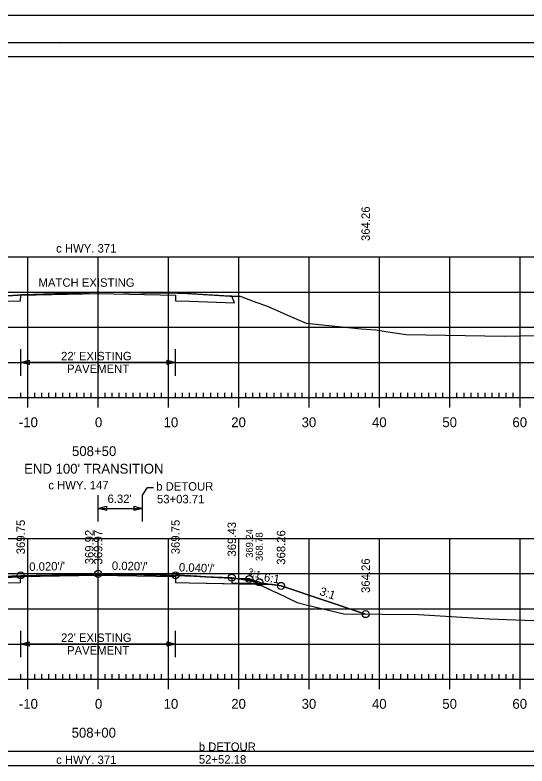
# Model space of a CAD drawing. Extents: x 1368910 to 1369601, y 380116 to 380950.
# Drawn here: x 1369068.4 to 1369141.2, y 380630.4 to 380737.1 of the extents above; entities that cross this region are included whole.
import ezdxf

# ---------------------------------------------------------------- set-up
doc = ezdxf.new("R2010")
doc.units = 0
for name, color, linetype in [('_STAGE 1 CUT', 7, 'Continuous'), ('_STAGE 1 FILL', 7, 'Continuous'), ('_STAGE 2 CUT', 7, 'Continuous'), ('_STAGE 3 CUT', 7, 'Continuous'), ('Default', 7, 'Continuous'), ('Notes', 7, 'Continuous'), ('R_Alt Surface', 7, 'Continuous'), ('R_Axis', 7, 'Continuous'), ('R_Axis Annot', 7, 'Continuous'), ('R_Border', 7, 'Continuous'), ('R_Border Plan-Plan', 7, 'Continuous'), ('R_Detour Surface', 7, 'Continuous'), ('R_Exist Surface', 7, 'Continuous'), ('R_Fin Surface', 7, 'Continuous'), ('R_Grid', 7, 'Continuous'), ('R_No Plot', 7, 'Continuous'), ('R_ROW Annot', 7, 'Continuous'), ('R_Xsect Elev', 7, 'Continuous'), ('R_Xsect Elev Detour', 7, 'Continuous'), ('R_Xsect Slope', 7, 'Continuous')]:
    doc.layers.add(name, color=color, linetype=linetype)

msp = doc.modelspace()

# ---------------------------------------------------------------- linework, layer by layer
at = {"layer": '_STAGE 1 CUT'}
for p, q in [((1369080.24, 380697.72), (1369080.24, 380697.55)), ((1369099.61, 380696.25), (1369099.25, 380697.17)), ((1369101.65, 380656.92), (1369101.64, 380656.93)), ((1369101.64, 380656.92), (1369101.65, 380656.92))]:
    msp.add_line(p, q, dxfattribs=at)
for points in [[(1369092.12, 380697.59), (1369091.55, 380697.62), (1369090.81, 380697.65), (1369090.64, 380697.65), (1369086.38, 380697.65), (1369086.34, 380697.65), (1369084.01, 380697.7), (1369083.9, 380697.71), (1369080.24, 380697.72)], [(1369080.24, 380697.55), (1369091.24, 380697.33), (1369091.25, 380696.5), (1369093.24, 380696.46), (1369099.61, 380696.25)], [(1369099.25, 380697.17), (1369099.24, 380697.17), (1369099.03, 380697.16), (1369098.12, 380697.22), (1369093.51, 380697.5), (1369092.12, 380697.59)], [(1369101.65, 380656.92), (1369101.64, 380656.93), (1369101.25, 380656.95), (1369100.27, 380657.02), (1369099.24, 380657.09), (1369099.03, 380657.1), (1369095.52, 380657.31), (1369094.27, 380657.39), (1369091.62, 380657.54), (1369091.24, 380657.56)], [(1369091.24, 380657.56), (1369091.24, 380657.51), (1369091.24, 380657.34)], [(1369091.24, 380657.34), (1369091.25, 380656.51), (1369093.24, 380656.47), (1369103.06, 380656.27)], [(1369101.64, 380656.93), (1369101.64, 380656.92)], [(1369103.06, 380656.27), (1369102.88, 380656.36), (1369102.25, 380656.66), (1369102.16, 380656.7), (1369101.65, 380656.92)]]:
    msp.add_lwpolyline(points, dxfattribs=at)
at = {"layer": '_STAGE 1 FILL'}
for p, q in [((1369104.97, 380656.23), (1369103.06, 380656.27)), ((1369103.06, 380656.27), (1369105.11, 380655.28))]:
    msp.add_line(p, q, dxfattribs=at)
for points in [[(1369118.26, 380652.01), (1369106.24, 380656.02), (1369104.97, 380656.23)], [(1369105.11, 380655.28), (1369105.71, 380655.03), (1369108.53, 380653.67), (1369110.01, 380653.27), (1369115.17, 380652.04), (1369118.26, 380652.01)]]:
    msp.add_lwpolyline(points, dxfattribs=at)
at = {"layer": '_STAGE 2 CUT'}
msp.add_line((1369080.24, 380697.55), (1369080.24, 380697.72), dxfattribs=at)
for points in [[(1369060.88, 380696.25), (1369067.24, 380696.46), (1369069.23, 380696.5), (1369069.24, 380697.33), (1369080.24, 380697.55)], [(1369080.09, 380697.72), (1369075.66, 380697.55), (1369075.58, 380697.54), (1369075.44, 380697.54), (1369069.62, 380697.38), (1369069.59, 380697.38), (1369069.38, 380697.37), (1369068.82, 380697.33), (1369062.24, 380696.88), (1369060.95, 380696.42)], [(1369080.19, 380697.72), (1369080.12, 380697.72), (1369080.09, 380697.72)], [(1369080.24, 380697.72), (1369080.21, 380697.72), (1369080.19, 380697.72)], [(1369069.24, 380657.33), (1369067.22, 380657.2), (1369062.25, 380656.95), (1369060.72, 380656.34)], [(1369067.24, 380656.47), (1369069.23, 380656.51), (1369069.24, 380657.33)]]:
    msp.add_lwpolyline(points, dxfattribs=at)
at = {"layer": '_STAGE 3 CUT'}
for points in [[(1369103.14, 380656.54), (1369101.74, 380657), (1369099.9, 380657.08)], [(1369099.9, 380657.08), (1369100.27, 380657.02), (1369102.16, 380656.7), (1369103.14, 380656.54)]]:
    msp.add_lwpolyline(points, dxfattribs=at)
at = {"layer": 'Default'}
msp.add_line((1369080.24, 380667.02), (1369086.56, 380667.02), dxfattribs=at)
msp.add_lwpolyline([(1369086.56, 380668.9), (1369087.24, 380670.01), (1369088.12, 380670.01)], dxfattribs=at)
at = {"layer": 'R_Alt Surface'}
for points in [[(1369055.52, 380656.23), (1369067.24, 380656.47), (1369069.23, 380656.51), (1369069.24, 380657.34), (1369080.24, 380657.56), (1369091.24, 380657.34), (1369091.25, 380656.51), (1369093.24, 380656.47), (1369104.97, 380656.23)], [(1369099.24, 380657.1), (1369099.24, 380656.43), (1369103.73, 380656.34)]]:
    msp.add_lwpolyline(points, dxfattribs=at)
at = {"layer": 'R_Axis'}
for p, q in [((1369070.24, 380681.36), (1369070.24, 380684.16)), ((1369080.24, 380681.36), (1369080.24, 380684.16)), ((1369090.24, 380681.36), (1369090.24, 380684.16)), ((1369100.24, 380681.36), (1369100.24, 380684.16)), ((1369110.24, 380681.36), (1369110.24, 380684.16)), ((1369120.24, 380681.36), (1369120.24, 380684.16)), ((1369130.24, 380681.36), (1369130.24, 380684.16)), ((1369140.24, 380681.36), (1369140.24, 380684.16)), ((1368940.24, 380682.76), (1369220.24, 380682.76)), ((1369069.24, 380682.76), (1369069.24, 380683.46)), ((1369071.24, 380682.76), (1369071.24, 380683.46)), ((1369072.24, 380682.76), (1369072.24, 380683.46)), ((1369073.24, 380682.76), (1369073.24, 380683.46)), ((1369074.24, 380682.76), (1369074.24, 380683.46)), ((1369075.24, 380682.76), (1369075.24, 380683.46)), ((1369076.24, 380682.76), (1369076.24, 380683.46)), ((1369077.24, 380682.76), (1369077.24, 380683.46)), ((1369078.24, 380682.76), (1369078.24, 380683.46)), ((1369079.24, 380682.76), (1369079.24, 380683.46)), ((1369081.24, 380682.76), (1369081.24, 380683.46)), ((1369082.24, 380682.76), (1369082.24, 380683.46)), ((1369083.24, 380682.76), (1369083.24, 380683.46)), ((1369084.24, 380682.76), (1369084.24, 380683.46)), ((1369085.24, 380682.76), (1369085.24, 380683.46)), ((1369086.24, 380682.76), (1369086.24, 380683.46)), ((1369087.24, 380682.76), (1369087.24, 380683.46)), ((1369088.24, 380682.76), (1369088.24, 380683.46)), ((1369089.24, 380682.76), (1369089.24, 380683.46)), ((1369091.24, 380682.76), (1369091.24, 380683.46)), ((1369092.24, 380682.76), (1369092.24, 380683.46)), ((1369093.24, 380682.76), (1369093.24, 380683.46)), ((1369094.24, 380682.76), (1369094.24, 380683.46)), ((1369095.24, 380682.76), (1369095.24, 380683.46)), ((1369096.24, 380682.76), (1369096.24, 380683.46)), ((1369097.24, 380682.76), (1369097.24, 380683.46)), ((1369098.24, 380682.76), (1369098.24, 380683.46)), ((1369099.24, 380682.76), (1369099.24, 380683.46)), ((1369101.24, 380682.76), (1369101.24, 380683.46)), ((1369102.24, 380682.76), (1369102.24, 380683.46)), ((1369103.24, 380682.76), (1369103.24, 380683.46)), ((1369104.24, 380682.76), (1369104.24, 380683.46)), ((1369105.24, 380682.76), (1369105.24, 380683.46)), ((1369106.24, 380682.76), (1369106.24, 380683.46)), ((1369107.24, 380682.76), (1369107.24, 380683.46)), ((1369108.24, 380682.76), (1369108.24, 380683.46)), ((1369109.24, 380682.76), (1369109.24, 380683.46)), ((1369111.24, 380682.76), (1369111.24, 380683.46)), ((1369112.24, 380682.76), (1369112.24, 380683.46)), ((1369113.24, 380682.76), (1369113.24, 380683.46)), ((1369114.24, 380682.76), (1369114.24, 380683.46)), ((1369115.24, 380682.76), (1369115.24, 380683.46)), ((1369116.24, 380682.76), (1369116.24, 380683.46)), ((1369117.24, 380682.76), (1369117.24, 380683.46)), ((1369118.24, 380682.76), (1369118.24, 380683.46)), ((1369119.24, 380682.76), (1369119.24, 380683.46)), ((1369121.24, 380682.76), (1369121.24, 380683.46)), ((1369122.24, 380682.76), (1369122.24, 380683.46)), ((1369123.24, 380682.76), (1369123.24, 380683.46)), ((1369124.24, 380682.76), (1369124.24, 380683.46)), ((1369125.24, 380682.76), (1369125.24, 380683.46)), ((1369126.24, 380682.76), (1369126.24, 380683.46)), ((1369127.24, 380682.76), (1369127.24, 380683.46)), ((1369128.24, 380682.76), (1369128.24, 380683.46)), ((1369129.24, 380682.76), (1369129.24, 380683.46)), ((1369131.24, 380682.76), (1369131.24, 380683.46)), ((1369132.24, 380682.76), (1369132.24, 380683.46)), ((1369133.24, 380682.76), (1369133.24, 380683.46)), ((1369134.24, 380682.76), (1369134.24, 380683.46)), ((1369135.24, 380682.76), (1369135.24, 380683.46)), ((1369136.24, 380682.76), (1369136.24, 380683.46)), ((1369137.24, 380682.76), (1369137.24, 380683.46)), ((1369138.24, 380682.76), (1369138.24, 380683.46)), ((1369139.24, 380682.76), (1369139.24, 380683.46)), ((1369070.24, 380641.36), (1369070.24, 380644.16)), ((1369080.24, 380641.36), (1369080.24, 380644.16)), ((1369090.24, 380641.36), (1369090.24, 380644.16)), ((1369100.24, 380641.36), (1369100.24, 380644.16)), ((1369110.24, 380641.36), (1369110.24, 380644.16)), ((1369120.24, 380641.36), (1369120.24, 380644.16)), ((1369130.24, 380641.36), (1369130.24, 380644.16)), ((1369140.24, 380641.36), (1369140.24, 380644.16)), ((1369069.24, 380642.76), (1369069.24, 380643.46)), ((1369071.24, 380642.76), (1369071.24, 380643.46)), ((1369072.24, 380642.76), (1369072.24, 380643.46)), ((1369073.24, 380642.76), (1369073.24, 380643.46)), ((1369074.24, 380642.76), (1369074.24, 380643.46)), ((1369075.24, 380642.76), (1369075.24, 380643.46)), ((1369076.24, 380642.76), (1369076.24, 380643.46)), ((1369077.24, 380642.76), (1369077.24, 380643.46)), ((1369078.24, 380642.76), (1369078.24, 380643.46)), ((1369079.24, 380642.76), (1369079.24, 380643.46)), ((1369081.24, 380642.76), (1369081.24, 380643.46)), ((1369082.24, 380642.76), (1369082.24, 380643.46)), ((1369083.24, 380642.76), (1369083.24, 380643.46)), ((1369084.24, 380642.76), (1369084.24, 380643.46)), ((1369085.24, 380642.76), (1369085.24, 380643.46)), ((1369086.24, 380642.76), (1369086.24, 380643.46)), ((1369087.24, 380642.76), (1369087.24, 380643.46)), ((1369088.24, 380642.76), (1369088.24, 380643.46)), ((1369089.24, 380642.76), (1369089.24, 380643.46)), ((1369091.24, 380642.76), (1369091.24, 380643.46)), ((1369092.24, 380642.76), (1369092.24, 380643.46)), ((1369093.24, 380642.76), (1369093.24, 380643.46)), ((1369094.24, 380642.76), (1369094.24, 380643.46)), ((1369095.24, 380642.76), (1369095.24, 380643.46)), ((1369096.24, 380642.76), (1369096.24, 380643.46)), ((1369097.24, 380642.76), (1369097.24, 380643.46)), ((1369098.24, 380642.76), (1369098.24, 380643.46)), ((1369099.24, 380642.76), (1369099.24, 380643.46)), ((1369101.24, 380642.76), (1369101.24, 380643.46)), ((1369102.24, 380642.76), (1369102.24, 380643.46)), ((1369103.24, 380642.76), (1369103.24, 380643.46)), ((1369104.24, 380642.76), (1369104.24, 380643.46)), ((1369105.24, 380642.76), (1369105.24, 380643.46)), ((1369106.24, 380642.76), (1369106.24, 380643.46)), ((1369107.24, 380642.76), (1369107.24, 380643.46)), ((1369108.24, 380642.76), (1369108.24, 380643.46)), ((1369109.24, 380642.76), (1369109.24, 380643.46)), ((1369111.24, 380642.76), (1369111.24, 380643.46)), ((1369112.24, 380642.76), (1369112.24, 380643.46)), ((1369113.24, 380642.76), (1369113.24, 380643.46)), ((1369114.24, 380642.76), (1369114.24, 380643.46)), ((1369115.24, 380642.76), (1369115.24, 380643.46)), ((1369116.24, 380642.76), (1369116.24, 380643.46)), ((1369117.24, 380642.76), (1369117.24, 380643.46)), ((1369118.24, 380642.76), (1369118.24, 380643.46)), ((1369119.24, 380642.76), (1369119.24, 380643.46)), ((1369121.24, 380642.76), (1369121.24, 380643.46)), ((1369122.24, 380642.76), (1369122.24, 380643.46)), ((1369123.24, 380642.76), (1369123.24, 380643.46)), ((1369124.24, 380642.76), (1369124.24, 380643.46)), ((1369125.24, 380642.76), (1369125.24, 380643.46)), ((1369126.24, 380642.76), (1369126.24, 380643.46)), ((1369127.24, 380642.76), (1369127.24, 380643.46)), ((1369128.24, 380642.76), (1369128.24, 380643.46)), ((1369129.24, 380642.76), (1369129.24, 380643.46)), ((1369131.24, 380642.76), (1369131.24, 380643.46)), ((1369132.24, 380642.76), (1369132.24, 380643.46)), ((1369133.24, 380642.76), (1369133.24, 380643.46)), ((1369134.24, 380642.76), (1369134.24, 380643.46)), ((1369135.24, 380642.76), (1369135.24, 380643.46)), ((1369136.24, 380642.76), (1369136.24, 380643.46)), ((1369137.24, 380642.76), (1369137.24, 380643.46)), ((1369138.24, 380642.76), (1369138.24, 380643.46)), ((1369139.24, 380642.76), (1369139.24, 380643.46)), ((1368940.24, 380642.76), (1369220.24, 380642.76))]:
    msp.add_line(p, q, dxfattribs=at)
at = {"layer": 'R_Border'}
for p, q in [((1368922.24, 380733.22), (1369238.42, 380733.22)), ((1369074.76, 380732.96), (1369074.76, 380732.96)), ((1369074.76, 380732.96), (1369074.76, 380732.96))]:
    msp.add_line(p, q, dxfattribs=at)
at = {"layer": 'R_Border Plan-Plan'}
msp.add_line((1368922.24, 380630.49), (1369238.42, 380630.49), dxfattribs=at)
at = {"layer": 'R_Detour Surface'}
msp.add_lwpolyline([(1369099.24, 380657.1), (1369101.74, 380657), (1369103.14, 380656.54), (1369103.73, 380656.34)], dxfattribs=at)
at = {"layer": 'R_Exist Surface'}
for points in [[(1369062.24, 380696.88), (1369068.82, 380697.33), (1369069.38, 380697.37), (1369069.59, 380697.38), (1369069.62, 380697.38), (1369075.44, 380697.54), (1369075.58, 380697.54), (1369075.66, 380697.55), (1369080.12, 380697.72), (1369080.19, 380697.72), (1369080.21, 380697.72), (1369083.9, 380697.71), (1369084.01, 380697.7), (1369086.34, 380697.65), (1369086.38, 380697.65), (1369090.64, 380697.65), (1369090.81, 380697.65), (1369091.55, 380697.62), (1369091.55, 380697.62), (1369092.12, 380697.59), (1369099.03, 380697.16), (1369099.61, 380697.18), (1369100.45, 380697.17), (1369102.3, 380696.47), (1369104.41, 380695.71), (1369107.04, 380694.5), (1369109.83, 380693.35), (1369117.62, 380692.51), (1369119.7, 380692.37), (1369121.13, 380692.17), (1369124.02, 380691.71), (1369129.59, 380691.65), (1369138.01, 380691.51), (1369148.63, 380691.72)], [(1369067.22, 380657.2), (1369069.54, 380657.35), (1369069.92, 380657.38), (1369070.52, 380657.38), (1369074.08, 380657.52), (1369074.69, 380657.54), (1369075.71, 380657.56), (1369079.62, 380657.65), (1369080.22, 380657.68), (1369080.5, 380657.69), (1369082.73, 380657.65), (1369085.59, 380657.63), (1369087.12, 380657.65), (1369089.07, 380657.62), (1369091.01, 380657.56), (1369091.62, 380657.54), (1369095.52, 380657.31), (1369099.03, 380657.1), (1369101.25, 380656.95), (1369101.64, 380656.93), (1369102.25, 380656.66), (1369105.11, 380655.28), (1369105.71, 380655.03), (1369108.53, 380653.67), (1369110.01, 380653.27), (1369115.17, 380652.04), (1369120.61, 380651.99), (1369125.77, 380651.94), (1369135.8, 380651.36), (1369143.39, 380651.06)]]:
    msp.add_lwpolyline(points, dxfattribs=at)
at = {"layer": 'R_Fin Surface'}
msp.add_lwpolyline([(1369034.95, 380652.59), (1369037.46, 380651.76), (1369041.46, 380651.76), (1369054.24, 380656.02), (1369055.52, 380656.23), (1369061.24, 380657.19), (1369069.24, 380657.51), (1369080.24, 380657.73), (1369091.24, 380657.51), (1369099.24, 380657.19), (1369104.97, 380656.23), (1369106.24, 380656.02), (1369118.26, 380652.01)], dxfattribs=at)
at = {"layer": 'R_Grid'}
for p, q in [((1368940.24, 380702.76), (1369220.24, 380702.76)), ((1369070.24, 380682.76), (1369070.24, 380702.76)), ((1369080.24, 380682.76), (1369080.24, 380702.76)), ((1369090.24, 380682.76), (1369090.24, 380702.76)), ((1369100.24, 380682.76), (1369100.24, 380702.76)), ((1369110.24, 380682.76), (1369110.24, 380702.76)), ((1369120.24, 380682.76), (1369120.24, 380702.76)), ((1369130.24, 380682.76), (1369130.24, 380702.76)), ((1369140.24, 380682.76), (1369140.24, 380702.76)), ((1368940.24, 380697.76), (1369220.24, 380697.76)), ((1368940.24, 380692.76), (1369220.24, 380692.76)), ((1368940.24, 380687.76), (1369220.24, 380687.76)), ((1368940.24, 380682.76), (1369220.24, 380682.76)), ((1368940.24, 380662.76), (1369220.24, 380662.76)), ((1369070.24, 380642.76), (1369070.24, 380662.76)), ((1369080.24, 380642.76), (1369080.24, 380662.76)), ((1369090.24, 380642.76), (1369090.24, 380662.76)), ((1369100.24, 380642.76), (1369100.24, 380662.76)), ((1369110.24, 380642.76), (1369110.24, 380662.76)), ((1369120.24, 380642.76), (1369120.24, 380662.76)), ((1369130.24, 380642.76), (1369130.24, 380662.76)), ((1369140.24, 380642.76), (1369140.24, 380662.76)), ((1368940.24, 380657.76), (1369220.24, 380657.76)), ((1368940.24, 380652.76), (1369220.24, 380652.76)), ((1368940.24, 380647.76), (1369220.24, 380647.76)), ((1368940.24, 380642.76), (1369220.24, 380642.76))]:
    msp.add_line(p, q, dxfattribs=at)
at = {"layer": 'R_No Plot'}
for points in [[(1368909.84, 380737.11), (1369243.18, 380737.11), (1369243.18, 380523.78), (1368909.84, 380523.78)], [(1369236.42, 380632.49), (1368924.24, 380632.49), (1368924.24, 380731.22), (1369173.78, 380731.22), (1369173.78, 380721.34), (1369191.32, 380721.34), (1369215.42, 380721.34), (1369215.42, 380699.01), (1369236.42, 380699.01)], [(1368924.24, 380731.22), (1369173.78, 380731.22), (1369173.78, 380721.34), (1369191.32, 380721.34), (1369215.42, 380721.34), (1369215.42, 380699.01), (1369236.42, 380699.01), (1369236.42, 380529.76), (1368924.24, 380529.76)]]:
    msp.add_lwpolyline(points, close=True, dxfattribs=at)
for centre in [(1369069.24, 380657.51), (1369080.24, 380657.73), (1369091.24, 380657.51), (1369099.24, 380657.19), (1369101.74, 380657), (1369103.14, 380656.54), (1369106.24, 380656.02), (1369118.26, 380652.01)]:
    msp.add_circle(centre, 0.5, dxfattribs=at)
at = {"layer": 'R_ROW Annot'}
for p, q in [((1369069.24, 380685.87), (1369069.24, 380689.64)), ((1369091.24, 380685.87), (1369091.24, 380689.64)), ((1369091.24, 380687.76), (1369069.24, 380687.76)), ((1369080.24, 380665.14), (1369080.24, 380668.9)), ((1369086.56, 380665.14), (1369086.56, 380668.9)), ((1369069.24, 380645.87), (1369069.24, 380649.64)), ((1369091.24, 380645.87), (1369091.24, 380649.64)), ((1369091.24, 380647.76), (1369069.24, 380647.76))]:
    msp.add_line(p, q, dxfattribs=at)
for points in [[(1369070.44, 380687.46), (1369069.24, 380687.76), (1369070.44, 380688.06)], [(1369090.04, 380688.06), (1369091.24, 380687.76), (1369090.04, 380687.46)], [(1369081.44, 380666.72), (1369080.24, 380667.02), (1369081.44, 380667.32)], [(1369085.36, 380667.32), (1369086.56, 380667.02), (1369085.36, 380666.72)], [(1369070.44, 380647.46), (1369069.24, 380647.76), (1369070.44, 380648.06)], [(1369090.04, 380648.06), (1369091.24, 380647.76), (1369090.04, 380647.46)]]:
    msp.add_lwpolyline(points, close=True, dxfattribs=at)

# ---------------------------------------------------------------- texts
at = {"layer": 'Notes'}
for s, p in [('c HWY. 371', (1369074.28, 380703.37)), ('MATCH EXISTING', (1369071.78, 380698.51)), ('c HWY. 147', (1369073.17, 380669.73)), ('b DETOUR', (1369088.5, 380669.55)), ('53+03.71', (1369088.61, 380667.75)), ('b DETOUR', (1369094.55, 380632.57)), ('c HWY. 371', (1369074.28, 380630.71)), ('52+52.18', (1369094.56, 380630.77))]:
    msp.add_text(s, height=1.2, dxfattribs=at).set_placement(p)
at = {"layer": 'R_Axis Annot'}
for s, p in [('-10', (1369068.98, 380678.56)), ('0', (1369079.79, 380678.56)), ('10', (1369089.55, 380678.56)), ('20', (1369099.16, 380678.56)), ('30', (1369109.16, 380678.56)), ('40', (1369119.16, 380678.56)), ('50', (1369129.16, 380678.56)), ('60', (1369139.12, 380678.56)), ('508+50', (1369076.53, 380674.46)), ("END 100' TRANSITION", (1369069.73, 380671.96)), ('-10', (1369068.98, 380638.56)), ('0', (1369079.79, 380638.56)), ('10', (1369089.55, 380638.56)), ('20', (1369099.16, 380638.56)), ('30', (1369109.16, 380638.56)), ('40', (1369119.16, 380638.56)), ('50', (1369129.16, 380638.56)), ('60', (1369139.12, 380638.56)), ('508+00', (1369076.48, 380634.46))]:
    msp.add_text(s, height=1.4, dxfattribs=at).set_placement(p)
at = {"layer": 'R_ROW Annot'}
for s, p in [("22' EXISTING", (1369074.98, 380688.06)), ('PAVEMENT', (1369075.83, 380686.26)), ("6.32'", (1369081.58, 380667.79)), ("22' EXISTING", (1369074.98, 380648.06)), ('PAVEMENT', (1369075.83, 380646.26))]:
    msp.add_text(s, height=1.2, dxfattribs=at).set_placement(p)
at = {"layer": 'R_Xsect Elev'}
for s, p in [('364.26', (1369118.86, 380705.01)), ('369.75', (1369069.84, 380660.51)), ('369.75', (1369091.84, 380660.51)), ('369.43', (1369099.84, 380660.19)), ('369.92', (1369079.59, 380659.08)), ('369.97', (1369080.84, 380659.06)), ('368.26', (1369106.84, 380659.02)), ('364.26', (1369118.86, 380655.01))]:
    msp.add_text(s, height=1.2, rotation=90, dxfattribs=at).set_placement(p)
at = {"layer": 'R_Xsect Elev Detour'}
for s, p in [('369.24', (1369102.24, 380660)), ('368.78', (1369103.64, 380659.54))]:
    msp.add_text(s, height=1, rotation=90, dxfattribs=at).set_placement(p)
at = {"layer": 'R_Xsect Slope'}
for s, height, rotation, p in [("0.020'/'", 1.2, 1.1458, (1369070.47, 380658.14)), ("0.020'/'", 1.2, 358.8542, (1369082.19, 380658.29)), ("0.040'/'", 1.2, 357.7094, (1369091.71, 380658.09)), ('3:1', 1, 341.5651, (1369101.41, 380657.64)), ('6:1', 1.2, 350.5377, (1369103.75, 380656.7)), ('3:1', 1.2, 341.5651, (1369111.62, 380654.75))]:
    msp.add_text(s, height=height, rotation=rotation, dxfattribs=at).set_placement(p)

doc.saveas('drawing.dxf')
